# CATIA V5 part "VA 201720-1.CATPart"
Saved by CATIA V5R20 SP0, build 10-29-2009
Part number: VA 201720-1
Revision: ANY
Definition: UNKNOWN
Nomenclature: VA 201720-1
Source: Unknown
Bounding box of the stored display mesh (mm): x -8.455 to 8.455, y 0 to 15.5, z -8.455 to 8.455
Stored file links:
  C:\Users\Utente\Desktop\IO LAVORO\3D X SITO CF\CUMSA\3D files VA\VA 201720\VA 201720-1.CATPart
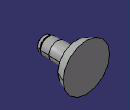
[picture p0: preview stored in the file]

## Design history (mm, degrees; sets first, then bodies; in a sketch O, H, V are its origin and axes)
Body1 "Revolución1" (main body)
  Solid1: solid without history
